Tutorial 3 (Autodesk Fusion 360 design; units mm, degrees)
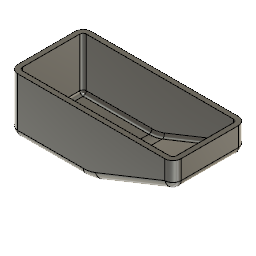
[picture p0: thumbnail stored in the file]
sketch "Sketch1" plane through (0, 0, 0) normal (0, 1, 0) x axis (1, 0, 0)
  line L1 (100, 0) -> (0, 0)
  line L2 (100, 15) -> (100, 0)
  line L3 (50, 35) -> (100, 15)
  line L4 (0, 35) -> (50, 35)
  line L5 (0, 0) -> (0, 35)
  point P1 (0, 0)
  point P2 (0, 0)
  point P3 (100, 0)
  point P4 (100, 15)
  point P6 (0, 35)
  point P5 (50, 35)
  coincident P1 P2
  horizontal L1
  perpendicular L1 L2
  parallel L1 L4
  vertical L5
  dimension "d1" distance P2 P3 = 100
  dimension "d2" distance P3 P4 = 15
  dimension "d3" distance P2 P6 = 35
  dimension "d4" distance P5 P6 = 50
extrude "Extrude1" new body sketch "Sketch1" distance 45
fillet "Fillet1" radius 25 5
fillet "Fillet2" radius 5
shell "Shell1" innerThickness 3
